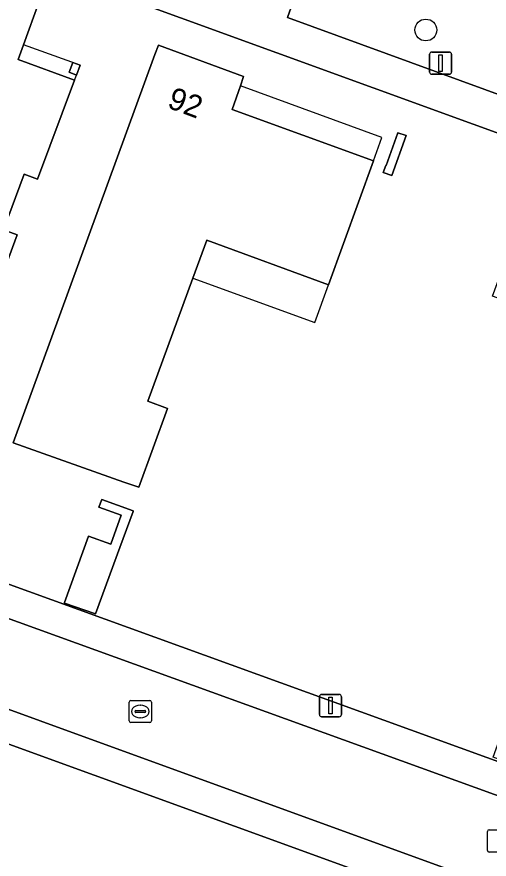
# Model space of a CAD drawing. Extents: x 155275 to 156265, y 382654 to 383635.
# Drawn here: x 155842.67 to 155863.88, y 382911.07 to 382948.93 of the extents above; entities that cross this region are included whole.
import ezdxf

# ---------------------------------------------------------------- set-up
doc = ezdxf.new("R2010")
doc.units = 0
for name, color, linetype in [('IMGEO_Boom', 7, 'Continuous'), ('IMGEO_Erf', 7, 'Continuous'), ('IMGEO_Groenvoorziening', 7, 'Continuous'), ('IMGEO_Kolk', 7, 'Continuous'), ('IMGEO_Lichtmast', 7, 'Continuous'), ('IMGEO_Muur', 7, 'Continuous'), ('IMGEO_Pand', 7, 'Continuous'), ('IMGEO_Pand_nummerreeks', 7, 'Continuous'), ('IMGEO_Pand_overbouw', 7, 'Continuous'), ('IMGEO_Rijbaan_lokaal_open', 7, 'Continuous'), ('IMGEO_Voetpad_open', 7, 'Continuous')]:
    doc.layers.add(name, color=color, linetype=linetype)

msp = doc.modelspace()

# ---------------------------------------------------------------- linework, layer by layer
at = {"layer": 'IMGEO_Boom'}
msp.add_circle((155861.033, 382948.344), 0.489, dxfattribs=at)
at = {"layer": 'IMGEO_Erf'}
msp.add_lwpolyline([(155780.113, 382945.991), (155867.203, 382914.393), (155867.255, 382914.495), (155864.055, 382915.66), (155866.086, 382921.27), (155869.286, 382920.105), (155870.988, 382924.735), (155867.774, 382925.878), (155869.239, 382929.918), (155864.546, 382931.622), (155866.017, 382935.658), (155864.025, 382936.374), (155865.931, 382941.549), (155874.418, 382938.44), (155873.731, 382936.48), (155875.083, 382935.986), (155876.306, 382939.329), (155819.213, 382960.092)], dxfattribs=at)
for points in [[(155839.795, 382931.32), (155841.21, 382930.822), (155841.044, 382930.35), (155841.403, 382930.224), (155839.409, 382924.565), (155839.05, 382924.691), (155835.511, 382925.998), (155837.817, 382932.357), (155835.614, 382933.153), (155838.111, 382940.031), (155833.823, 382941.592), (155837.55, 382951.859), (155843.674, 382949.631), (155842.963, 382947.676), (155842.724, 382947.018), (155845.261, 382946.095), (155843.597, 382941.639), (155842.987, 382941.864), (155842.064, 382939.359), (155842.674, 382939.134)], [(155848.552, 382931.655), (155849.437, 382931.331), (155848.139, 382927.79), (155847.471, 382928.02), (155842.492, 382929.78), (155848.868, 382947.236), (155849.024, 382947.663), (155852.849, 382946.25), (155852.703, 382945.834), (155852.33, 382944.769), (155858.679, 382942.46), (155856.664, 382936.891), (155851.198, 382938.894), (155850.576, 382937.192)], [(155845.345, 382946.32), (155845.016, 382946.442), (155845.177, 382946.877), (155845.507, 382946.758)], [(155859.234, 382942.258), (155859.26, 382942.249), (155859.633, 382943.301), (155859.782, 382943.721), (155860.147, 382943.599), (155859.504, 382941.802), (155859.118, 382941.941)], [(155858.578, 382910.318), (155778.11, 382939.582), (155776.003, 382933.692), (155781.968, 382931.558), (155779.643, 382925.014), (155784.554, 382923.227), (155784.283, 382922.477), (155785.216, 382922.133), (155781.233, 382911.153), (155780.932, 382911.263), (155781.358, 382912.438), (155777.396, 382913.993), (155776.968, 382912.818), (155770.335, 382915.238), (155770.972, 382916.985), (155770.033, 382917.328), (155767.593, 382910.639), (155854.498, 382879.089), (155856.191, 382884.092), (155849.881, 382886.353), (155855.747, 382902.481), (155860.835, 382896.859), (155862.363, 382901.052), (155857.263, 382906.66)], [(155847.893, 382926.731), (155847.884, 382926.706), (155847.29, 382925.084), (155846.193, 382922.093), (155844.807, 382922.586), (155844.808, 382922.613), (155845.884, 382925.592), (155846.881, 382925.232), (155847.35, 382926.53), (155846.353, 382926.89), (155846.482, 382927.247)]]:
    msp.add_lwpolyline(points, close=True, dxfattribs=at)
at = {"layer": 'IMGEO_Groenvoorziening'}
msp.add_lwpolyline([(155858.099, 382958.145), (155854.818, 382948.899), (155876.986, 382940.814), (155880.309, 382950.108)], close=True, dxfattribs=at)
at = {"layer": 'IMGEO_Kolk'}
for p, q in [((155847.785, 382918.21), (155848.637, 382918.21)), ((155847.71, 382917.284), (155847.71, 382918.136)), ((155848.198, 382917.99), (155848.223, 382917.99)), ((155848.711, 382918.136), (155848.711, 382917.284)), ((155847.969, 382917.704), (155847.969, 382917.716)), ((155848.407, 382917.667), (155848.009, 382917.667)), ((155848.012, 382917.753), (155848.41, 382917.753)), ((155848.221, 382917.43), (155848.196, 382917.43)), ((155848.453, 382917.716), (155848.453, 382917.704)), ((155848.637, 382917.21), (155847.785, 382917.21)), ((155863.803, 382911.465), (155863.803, 382912.317)), ((155863.878, 382912.391), (155864.73, 382912.391)), ((155864.73, 382911.391), (155863.878, 382911.391))]:
    msp.add_line(p, q, dxfattribs=at)
for points in [[(155847.785, 382918.21), (155848.637, 382918.21)], [(155847.71, 382917.284), (155847.71, 382918.136)], [(155848.711, 382918.136), (155848.711, 382917.284)], [(155848.637, 382917.21), (155847.785, 382917.21)], [(155863.803, 382911.465), (155863.803, 382912.317)], [(155863.878, 382912.391), (155864.73, 382912.391)], [(155864.73, 382911.391), (155863.878, 382911.391)]]:
    msp.add_lwpolyline(points, dxfattribs=at)
for centre, radius, start, end in [((155847.787, 382918.134), 0.0765, 91.552, 178.448), ((155847.787, 382918.134), 0.0765, 91.552, 178.448), ((155848.635, 382918.134), 0.0765, 1.552, 88.448), ((155848.635, 382918.134), 0.0765, 1.552, 88.448), ((155848.009, 382917.713), 0.0403, 85.8775, 175.7526), ((155848.006, 382917.703), 0.0366, 178.938, 274.7102), ((155848.41, 382917.71), 0.043, 264.8664, 352.4533), ((155848.414, 382917.715), 0.0386, 1.7309, 96.639), ((155847.787, 382917.286), 0.0765, 181.552, 268.448), ((155847.787, 382917.286), 0.0765, 181.552, 268.448), ((155848.635, 382917.286), 0.0765, 271.552, 358.448), ((155848.635, 382917.286), 0.0765, 271.552, 358.448), ((155863.88, 382912.315), 0.0765, 91.552, 178.448), ((155863.88, 382912.315), 0.0765, 91.552, 178.448), ((155863.88, 382911.467), 0.0765, 181.552, 268.448), ((155863.88, 382911.467), 0.0765, 181.552, 268.448)]:
    msp.add_arc(centre, radius, start, end, dxfattribs=at)
for centre, major_axis, ratio, start_param, end_param in [((155848.197, 382917.71), (-0.387, 0.002), 0.722429, 4.712389, 7.853982), ((155848.222, 382917.71), (-0.39, 0.002), 0.717154, 1.570796, 4.712389)]:
    msp.add_ellipse(centre, major_axis=major_axis, ratio=ratio, start_param=start_param, end_param=end_param, dxfattribs=at)
at = {"layer": 'IMGEO_Lichtmast'}
for p, q in [((155861.302, 382947.353), (155862.092, 382947.353)), ((155862.092, 382947.353), (155861.302, 382947.353)), ((155861.202, 382946.453), (155861.202, 382947.253)), ((155861.202, 382947.253), (155861.202, 382946.453)), ((155862.192, 382947.253), (155862.192, 382946.453)), ((155862.192, 382946.453), (155862.192, 382947.253)), ((155862.092, 382946.353), (155861.302, 382946.353)), ((155861.302, 382946.353), (155862.092, 382946.353)), ((155856.255, 382917.575), (155856.255, 382918.375)), ((155856.255, 382918.375), (155856.255, 382917.575)), ((155856.355, 382918.475), (155857.145, 382918.475)), ((155857.145, 382918.475), (155856.355, 382918.475)), ((155857.245, 382918.375), (155857.245, 382917.575)), ((155857.245, 382917.575), (155857.245, 382918.375)), ((155857.145, 382917.475), (155856.355, 382917.475)), ((155856.355, 382917.475), (155857.145, 382917.475))]:
    msp.add_line(p, q, dxfattribs=at)
for points in [[(155861.622, 382947.228), (155861.772, 382947.228), (155861.772, 382946.478), (155861.622, 382946.478), (155861.622, 382947.228)], [(155856.675, 382918.35), (155856.825, 382918.35), (155856.825, 382917.6), (155856.675, 382917.6), (155856.675, 382918.35)]]:
    msp.add_lwpolyline(points, dxfattribs=at)
for centre, start, end in [((155861.302, 382947.253), 90, 180), ((155861.302, 382947.253), 90, 180), ((155862.092, 382947.253), 0, 90), ((155862.092, 382947.253), 360, 90), ((155861.302, 382946.453), 180, 270), ((155861.302, 382946.453), 180, 270), ((155862.092, 382946.453), 270, 0), ((155862.092, 382946.453), 270, 0), ((155856.355, 382918.375), 90, 180), ((155856.355, 382918.375), 90, 180), ((155857.145, 382918.375), 0, 90), ((155857.145, 382918.375), 360, 90), ((155856.355, 382917.575), 180, 270), ((155856.355, 382917.575), 180, 270), ((155857.145, 382917.575), 270, 0), ((155857.145, 382917.575), 270, 0)]:
    msp.add_arc(centre, 0.1, start, end, dxfattribs=at)
at = {"layer": 'IMGEO_Muur'}
for points in [[(155859.26, 382942.249), (155859.234, 382942.258), (155859.118, 382941.941), (155859.504, 382941.802), (155860.147, 382943.599), (155859.782, 382943.721), (155859.633, 382943.301)], [(155847.29, 382925.084), (155847.884, 382926.706), (155847.893, 382926.731), (155846.482, 382927.247), (155846.353, 382926.89), (155847.35, 382926.53), (155846.881, 382925.232), (155845.884, 382925.592), (155844.808, 382922.613), (155844.807, 382922.586), (155846.193, 382922.093)]]:
    msp.add_lwpolyline(points, close=True, dxfattribs=at)
at = {"layer": 'IMGEO_Pand'}
for points in [[(155845.261, 382946.095), (155842.724, 382947.018), (155842.963, 382947.676), (155843.674, 382949.631), (155837.55, 382951.859), (155833.823, 382941.592), (155838.111, 382940.031), (155835.614, 382933.153), (155837.817, 382932.357), (155835.511, 382925.998), (155839.05, 382924.691), (155841.044, 382930.35), (155841.21, 382930.822), (155839.795, 382931.32), (155842.674, 382939.134), (155842.064, 382939.359), (155842.987, 382941.864), (155843.597, 382941.639)], [(155850.576, 382937.192), (155851.198, 382938.894), (155856.664, 382936.891), (155858.679, 382942.46), (155852.33, 382944.769), (155852.703, 382945.834), (155852.849, 382946.25), (155849.024, 382947.663), (155848.868, 382947.236), (155842.492, 382929.78), (155847.471, 382928.02), (155848.139, 382927.79), (155849.437, 382931.331), (155848.552, 382931.655)], [(155845.507, 382946.758), (155845.177, 382946.877), (155845.016, 382946.442), (155845.345, 382946.32)]]:
    msp.add_lwpolyline(points, close=True, dxfattribs=at)
at = {"layer": 'IMGEO_Pand_overbouw'}
for points in [[(155845.261, 382946.095), (155845.345, 382946.32), (155845.507, 382946.758), (155842.963, 382947.676), (155842.724, 382947.018)], [(155852.703, 382945.834), (155852.33, 382944.769), (155858.679, 382942.46), (155859.059, 382943.511)], [(155851.198, 382938.894), (155850.576, 382937.192), (155856.05, 382935.196), (155856.664, 382936.891)]]:
    msp.add_lwpolyline(points, close=True, dxfattribs=at)
at = {"layer": 'IMGEO_Rijbaan_lokaal_open'}
msp.add_lwpolyline([(155779.611, 382944.594), (155777.389, 382945.399), (155777.321, 382945.404), (155773.631, 382946.766), (155772.36, 382943.272), (155776.11, 382941.886), (155776.209, 382941.85), (155778.386, 382941.058), (155778.616, 382940.974), (155865.403, 382909.39), (155867.798, 382908.519), (155871.528, 382907.192), (155872.823, 382910.756), (155869.136, 382912.156), (155866.718, 382913.032)], close=True, dxfattribs=at)
at = {"layer": 'IMGEO_Voetpad_open'}
for points in [[(155817.258, 382974.414), (155794.244, 382982.888), (155793.451, 382981.639), (155809.733, 382975.708), (155806.295, 382966.522), (155790.126, 382972.445), (155789.359, 382971.074), (155819.213, 382960.092), (155876.306, 382939.329), (155876.986, 382940.814), (155854.818, 382948.899), (155858.099, 382958.145), (155880.309, 382950.108), (155880.792, 382951.626), (155845.91, 382964.137)], [(155780.113, 382945.991), (155779.611, 382944.594), (155866.718, 382913.032), (155867.203, 382914.393)], [(155778.616, 382940.974), (155778.11, 382939.582), (155858.578, 382910.318), (155864.887, 382908.023), (155865.403, 382909.39)]]:
    msp.add_lwpolyline(points, close=True, dxfattribs=at)

# ---------------------------------------------------------------- texts
at = {"layer": 'IMGEO_Pand_nummerreeks'}
msp.add_text('92', height=1, rotation=339.5282, dxfattribs=at).set_placement((155849.375, 382944.871))

doc.saveas('drawing.dxf')
